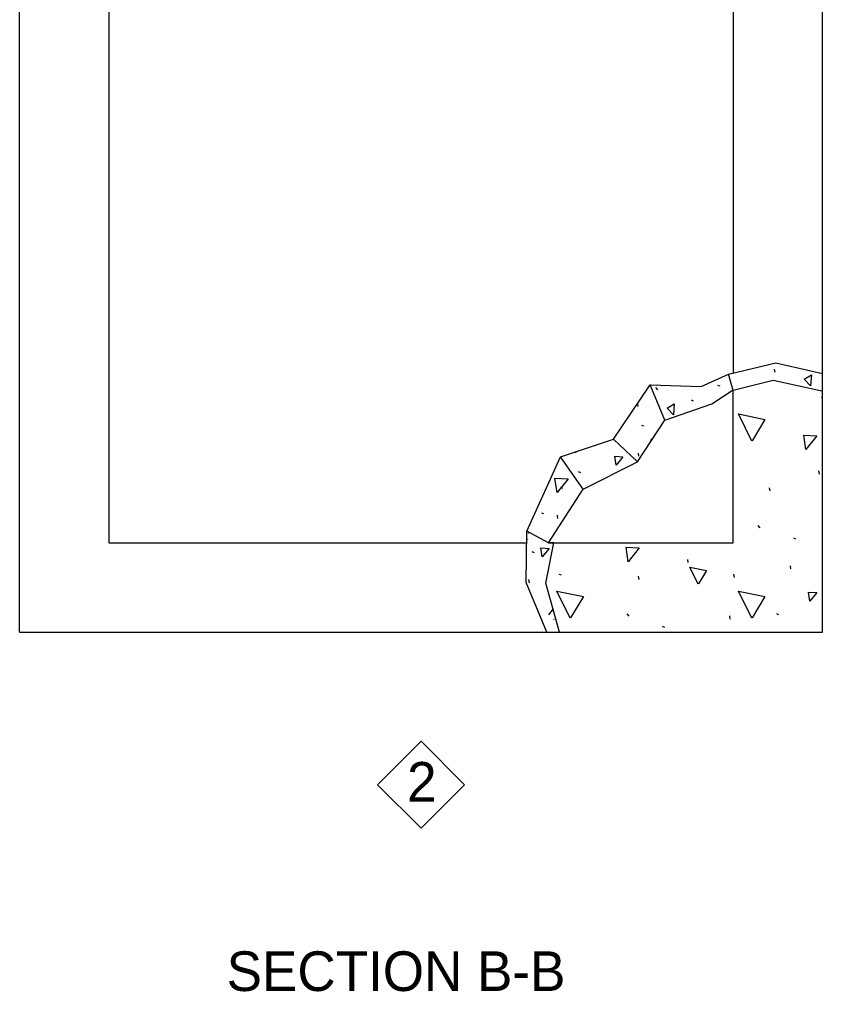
# Model space of a CAD drawing. Extents: x 49991.4 to 50029.7, y 49987.6 to 50011.4.
# Drawn here: x 50022.951 to 50024.571, y 49990.286 to 49992.248 of the extents above; entities that cross this region are included whole.
import ezdxf

# ---------------------------------------------------------------- set-up
doc = ezdxf.new("R2010")
doc.units = 0
for name, color, linetype in [('Level 1', 7, 'Continuous'), ('Level 10', 7, 'Continuous'), ('Level 2', 7, 'Continuous'), ('Level 20', 7, 'Continuous'), ('Level 9', 7, 'Continuous')]:
    doc.layers.add(name, color=color, linetype=linetype)

msp = doc.modelspace()

# ---------------------------------------------------------------- linework, layer by layer
at = {"layer": 'Level 1'}
for p, q in [((50022.9513, 49991.0114), (50022.9513, 49993.5314)), ((50024.3913, 49992.7735), (50024.3913, 49991.5344)), ((50024.0295, 49991.1914), (50024.3913, 49991.1914)), ((50022.9513, 49991.0114), (50024.5713, 49991.0114))]:
    msp.add_line(p, q, dxfattribs=at)
for points in [[(50023.1313, 49992.7735), (50023.1313, 49991.1914), (50023.9743, 49991.1914)], [(50024.5713, 49991.0114), (50024.5713, 49992.7735)], [(50024.0153, 49991.0114), (50023.9735, 49991.1114), (50023.9746, 49991.2152), (50024.0429, 49991.3656), (50024.1496, 49991.4012), (50024.2234, 49991.5106), (50024.3263, 49991.507), (50024.3815, 49991.5321), (50024.4769, 49991.5548), (50024.5713, 49991.5336)], [(50024.5697, 49991.4976), (50024.4714, 49991.5193), (50024.3913, 49991.4994), (50024.3815, 49991.5321)], [(50024.0188, 49991.1915), (50024.0884, 49991.2997), (50024.198, 49991.355), (50024.2531, 49991.4391), (50024.3482, 49991.472), (50024.3913, 49991.5004)], [(50024.3913, 49991.1914), (50024.3913, 49991.4994)], [(50024.0409, 49991.0114), (50024.0134, 49991.1104), (50024.0295, 49991.1914), (50024.0188, 49991.1915), (50023.9746, 49991.2152)]]:
    msp.add_lwpolyline(points, dxfattribs=at)
at = {"layer": 'Level 10'}
for p, q in [((50024.2531, 49991.4391), (50024.2234, 49991.5106)), ((50024.198, 49991.355), (50024.1496, 49991.4012)), ((50024.0884, 49991.2997), (50024.0429, 49991.3656)), ((50023.9756, 49991.1995), (50023.9764, 49991.1984)), ((50023.9743, 49991.1874), (50023.975, 49991.1889)), ((50024.0188, 49991.1915), (50024.0295, 49991.1914)), ((50024.0291, 49991.1911), (50024.0293, 49991.1915)), ((50024.0291, 49991.0368), (50024.0299, 49991.0385))]:
    msp.add_line(p, q, dxfattribs=at)
for points in [[(50024.2362, 49991.5095), (50024.2365, 49991.5101)], [(50024.2379, 49991.5101), (50024.2362, 49991.5095)], [(50024.1462, 49991.4001), (50024.1469, 49991.3996), (50024.1409, 49991.3977)], [(50024.1409, 49991.3977), (50024.1413, 49991.3984)], [(50024.2249, 49991.3977), (50024.2272, 49991.4024), (50024.2284, 49991.4014)], [(50024.2263, 49991.3981), (50024.2249, 49991.3977)]]:
    msp.add_lwpolyline(points, dxfattribs=at)
at = {"layer": 'Level 20'}
msp.add_lwpolyline([(50023.7613, 49990.7914), (50023.849, 49990.7036), (50023.7613, 49990.6158), (50023.6735, 49990.7036)], close=True, dxfattribs=at)
at = {"layer": 'Level 9'}
for p, q in [((50024.4757, 49991.5359), (50024.4746, 49991.5424)), ((50024.2346, 49991.5052), (50024.2386, 49991.5006)), ((50024.3594, 49991.5102), (50024.3638, 49991.5084)), ((50024.3062, 49991.4805), (50024.3106, 49991.4786)), ((50024.5686, 49991.4855), (50024.5713, 49991.4844)), ((50024.2059, 49991.4294), (50024.2104, 49991.4276)), ((50024.201, 49991.3665), (50024.1998, 49991.373)), ((50024.5648, 49991.3303), (50024.5637, 49991.3368)), ((50024.0786, 49991.3359), (50024.0831, 49991.334)), ((50024.0425, 49991.304), (50024.0469, 49991.3021)), ((50024.4656, 49991.2964), (50024.4645, 49991.3028)), ((50024.0042, 49991.2526), (50024.0086, 49991.2507)), ((50024.0375, 49991.241), (50024.0364, 49991.2475)), ((50024.4409, 49991.2266), (50024.4448, 49991.222)), ((50024.5125, 49991.2019), (50024.5169, 49991.2)), ((50023.985, 49991.1742), (50023.9895, 49991.1724)), ((50024.3003, 49991.1519), (50024.2992, 49991.1584)), ((50024.5075, 49991.139), (50024.5064, 49991.1454)), ((50024.0396, 49991.1287), (50024.044, 49991.1269)), ((50024.2011, 49991.118), (50024.2, 49991.1244)), ((50024.3938, 49991.1218), (50024.3926, 49991.1283)), ((50023.9801, 49991.1113), (50023.9789, 49991.1178)), ((50024.1765, 49991.0482), (50024.1804, 49991.0436)), ((50024.3852, 49991.038), (50024.3841, 49991.0445)), ((50024.4781, 49991.0492), (50024.4825, 49991.0474)), ((50024.248, 49991.0235), (50024.2524, 49991.0216))]:
    msp.add_line(p, q, dxfattribs=at)
for points in [[(50024.5468, 49991.5085), (50024.5344, 49991.5222), (50024.5487, 49991.5307), (50024.5468, 49991.5085)], [(50024.2247, 49991.5105), (50024.2239, 49991.5093)], [(50024.1993, 49991.4667), (50024.1983, 49991.4734)], [(50024.2703, 49991.45), (50024.2579, 49991.4637), (50024.2722, 49991.4722), (50024.2703, 49991.45)], [(50024.4286, 49991.3969), (50024.4017, 49991.4518), (50024.455, 49991.4405), (50024.4292, 49991.3978)], [(50024.5377, 49991.3802), (50024.5334, 49991.4092), (50024.5599, 49991.4079), (50024.5377, 49991.3802)], [(50024.0743, 49991.3761), (50024.072, 49991.3731)], [(50024.072, 49991.3731), (50024.0717, 49991.3752)], [(50024.1547, 49991.3482), (50024.152, 49991.3665), (50024.1686, 49991.3656), (50024.1547, 49991.3482)], [(50024.0358, 49991.293), (50024.0315, 49991.322), (50024.058, 49991.3207), (50024.0358, 49991.293)], [(50023.9784, 49991.2115), (50023.9781, 49991.2133)], [(50023.9793, 49991.2127), (50023.9784, 49991.2115)], [(50024.0058, 49991.1632), (50024.0031, 49991.1815), (50024.0197, 49991.1806), (50024.0058, 49991.1632)], [(50024.1793, 49991.1537), (50024.1751, 49991.1827), (50024.2015, 49991.1814), (50024.1793, 49991.1537)], [(50024.3204, 49991.1083), (50024.3035, 49991.1428), (50024.3371, 49991.1357), (50024.3208, 49991.1089)], [(50024.0624, 49991.0395), (50024.0355, 49991.0943), (50024.0889, 49991.0831), (50024.063, 49991.0403)], [(50024.4286, 49991.0395), (50024.4017, 49991.0943), (50024.455, 49991.0831), (50024.4292, 49991.0403)], [(50024.5457, 49991.074), (50024.543, 49991.0922), (50024.5597, 49991.0914), (50024.5457, 49991.074)], [(50024.0279, 49991.0583), (50024.0183, 49991.0463)]]:
    msp.add_lwpolyline(points, dxfattribs=at)

# ---------------------------------------------------------------- texts
at = {"layer": 'Level 2'}
msp.add_text('SECTION B-B', height=0.08, dxfattribs=at).set_placement((50023.3692, 49990.2873))
at = {"layer": 'Level 20'}
msp.add_text('2', height=0.08, dxfattribs=at).set_placement((50023.7332, 49990.6694))

doc.saveas('drawing.dxf')
